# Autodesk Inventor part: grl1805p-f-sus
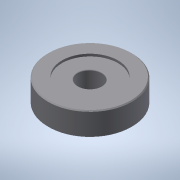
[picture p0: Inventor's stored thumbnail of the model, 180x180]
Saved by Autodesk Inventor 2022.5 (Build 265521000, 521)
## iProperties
Created: 2016-12
Part Number: grl1805p-f-sus
Material: 一般
Document SubType Name: Modeling
Designer: imaocorp
Density: 1 g/cm^3
Appearance: 既定
Author: imaocorp
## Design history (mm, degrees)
node "grl1805p-f-sus.x_t1"
node "grl1805p-f-sus"
node "Base1"
